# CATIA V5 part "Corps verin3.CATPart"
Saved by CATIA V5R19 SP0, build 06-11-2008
Part number: Corps verin3
Bounding box of the stored display mesh (mm): x 1.043 to 52.671, y -55.491 to -45, z 75.494 to 157.988
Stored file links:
  G:\EU_thinkMotion\CFAO_2010\MMS_groupe1\MMS_groupe1\A reprendre\OK\glenerrant\glenerrant\glenerrant\Corps verin3.CATPart
  G:\EU_thinkMotion\CFAO_2010\MMS_groupe1\MMS_groupe1\A reprendre\OK\glenerrant\glenerrant\glenerrant\tige verin3.CATPart
  C:\Users\Gauthier\Documents\IFMA\Projet CFAO\LENERRANT\Systeme.CATProduct
  G:\EU_thinkMotion\CFAO_2010\MMS_groupe1\MMS_groupe1\A reprendre\OK\glenerrant\glenerrant\glenerrant\Squelette de base.CATPart
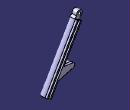
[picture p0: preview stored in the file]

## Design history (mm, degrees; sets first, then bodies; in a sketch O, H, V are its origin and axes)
Parameters
  `Longueur corps verin 3` = 88 mm
Set1
  Point1: (5, -51, 154)
  Point2: (89, -51, 8)
  Point3: (5, 51, 154)
  Line1: type PtPt, FirstPoint Point1, SecondPoint Point3
  Line2: type PtPt, FirstPoint Point1, SecondPoint Point2
  Plane1: type Normal, Curve Line1, RefPoint Point1
  Plane2: type Normal, Curve Line2, RefPoint Point1
  Plane3: type Offset, RefPlane Plane1, Offset 4
  Point4: (17, -51, 101)
Body1 (main body)
  Sketch1 on Plane1, origin (0, -51, 0), H (-1, 0, 0), V (0, 0, 1)
    arc A1 centre (-5, 154) radius 4 from (-4.097, 150.1033) to (-8.8226, 152.8221) ccw
    point P1 (-5, 154)
    reference projected point E1 (-5, 154) from Point1
    line L1 (-4.097, 150.1033) -> (-4.0917, 146.5552)
    line L2 (-8.8226, 152.8221) -> (-11.8927, 151.0435)
    point P5 (-11.8927, 151.0435)
    line L3 (-11.8927, 151.0435) -> (-4.0917, 146.5552)
    reference intersected line E2 through (65.3241, 113.5395) direction (0.8668, -0.4987) from Plane2
    reference projected line E3 (-5, 154) -> (-89, 8) from Line2
    reference projected point E4 (-5, 154) from Point1
    circle A2 centre (-5, 154) radius 2
    point P6 (-5, 154)
    reference projected point E5 (-5, 154) from Point1
    radius A1 = 4
    length L3 = 9
    distance P5 E3 = 4.5
    angle L1 L3 = 60
    distance L3 E4 = 6
    angle L2 L3 = 60
    radius A2 = 2
    coincidence: P1 E1, E5 P6
    parallelism: L3 E2
  Pad1: profile Sketch1, direction (0, 1, 0), length 3, opposite side length 3
  Sketch2 on Plane2, origin (-65.3241, 0, 113.5395), H (0, 1, 0), V (0.8668, 0, 0.4987)
    line L1 (-48.1123, 77.6815) -> (-45, 77.6815)
    line L2 (-45, 79.4315) -> (-47, 79.4315)
    line L3 (-47, 82.4315) -> (-45, 82.4315)
    line L4 (-45, 84.1815) -> (-47.6901, 84.1815)
    line L5 (-47, 79.4315) -> (-47, 82.4315)
    line L6 (-45, 77.6815) -> (-45, 79.4315)
    line L7 (-45, 82.4315) -> (-45, 84.1815)
    reference projected point E1 (-51, 81.1328) from Point1
    reference projected point E2 (-51, 81.1328) from Point1
    arc A1 centre (-51, 81.1328) radius 4.5 from (-47.6901, 84.1815) to (-48.1123, 77.6815) ccw
    point P9 (-51, 81.1328)
    reference projected point E3 (-51, 81.1328) from Point1
    length L5 = 3
    distance L1 L2 = 1.75
    distance L3 L4 = 1.75
    distance L5 L7 = 2
    distance E1 L5 = 4
    distance L5 L6 = 2
    distance E2 L2 = 1.7013
    radius A1 = 4.5
    horizontal: L1 H, L2 H, L3 H
    vertical: L5 V
    parallelism: L7 L6, L3 L2
    coincidence: P9 E3
  Pad2: profile Sketch2, direction (0.4987, 0, -0.8668), length 88 {= `Longueur corps verin 3`}, opposite side length -6
  Sketch3 on end face of Pad2, origin (48.8851, -51, 77.7235), H (0.8668, 0, 0.4987), V (0, -1, 0)
    point P1 (0, 0)
  Hole1: placed by Sketch3, at (48.8851, -51, 77.7235) direction (-0.4987, 0, 0.8668), diameter 5, depth 80
  Sketch4 on face of Pad2 from Sketch2.L6, origin (0, -45, 0), H (-1, 0, 0), V (0, 0, 1)
    arc A1 centre (-17, 101) radius 3 from (-16.205, 98.1073) to (-16.6136, 103.975) ccw
    point P1 (-17, 101)
    reference projected point E1 (-17, 101) from Point4
    line L1 (-16.205, 98.1073) -> (-36.3633, 92.5669)
    line L2 (-16.6136, 103.975) -> (-28.8829, 105.5685)
    point P5 (-28.8829, 105.5685)
    line L3 (-28.8829, 105.5685) -> (-36.3633, 92.5669)
    reference projected line E2 (-5.0007, 147.0782) -> (-45.8936, 76.0024) from edge [face of Pad2 from Sketch2.L6 | face of Pad2 from Sketch2.L1]
    reference projected point E3 (-5, 154) from Point1
    radius A1 = 3
    distance P5 E3 = 54
    length L3 = 15
    coincidence: P1 E1, E2 L3
    tangency: L2 A1, L1 A1
  Pad3: profile Sketch4, direction (0, -1, 0), length 3
  Sketch5 on end face of Pad3, origin (0, -48, 0), H (1, 0, 0), V (0, 0, 1)
    circle A1 centre (17, 101) radius 2
    point P1 (17, 101)
    reference projected point E1 (17, 101) from Point4
    radius A1 = 2
    coincidence: P1 E1
  Pad4: profile Sketch5, direction (0, -1, 0), length 6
